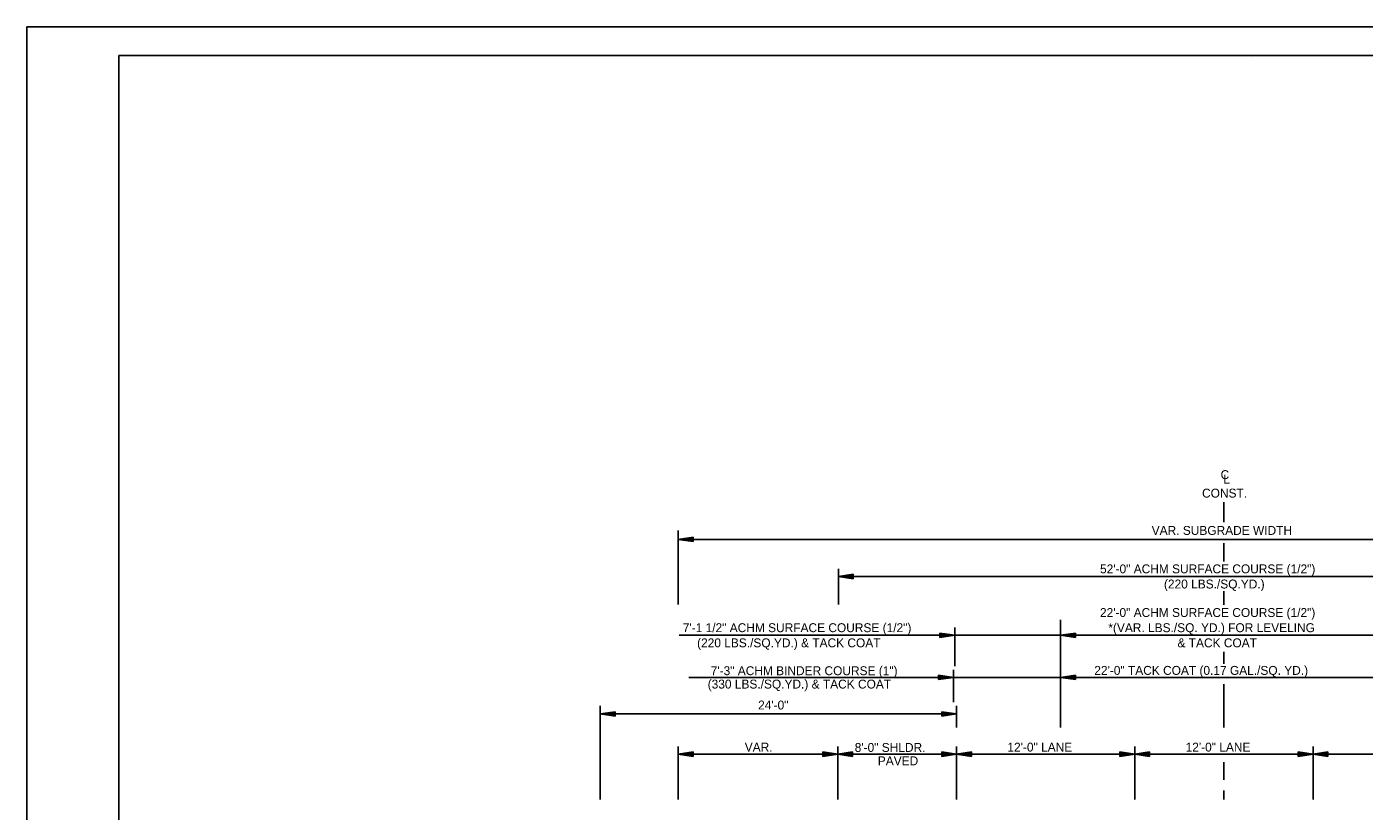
# Model space of a CAD drawing. Extents: x 1371763 to 1372860, y 385599 to 385872.
# Drawn here: x 1371763.4 to 1371853.4, y 385652.4 to 385705.3 of the extents above; entities that cross this region are included whole.
import ezdxf

# ---------------------------------------------------------------- set-up
doc = ezdxf.new("R2010")
doc.units = 0
for name, color, linetype in [('R_Border', 7, 'Continuous'), ('R_Draft', 7, 'Continuous'), ('R_No Plot', 7, 'Continuous')]:
    doc.layers.add(name, color=color, linetype=linetype)

msp = doc.modelspace()

# ---------------------------------------------------------------- linework, layer by layer
at = {"layer": 'R_Border'}
for p, q in [((1371769.555, 385703.307), (1371927.645, 385703.307)), ((1371769.555, 385600.577), (1371769.555, 385703.307)), ((1371845.815, 385703.177), (1371845.815, 385703.177)), ((1371845.815, 385703.177), (1371845.815, 385703.177))]:
    msp.add_line(p, q, dxfattribs=at)
at = {"layer": 'R_Draft'}
for p, q in [((1371843.971, 385671.877), (1371843.971, 385673.227)), ((1371807.224, 385666.329), (1371807.224, 385671.327)), ((1371808.224, 385670.877), (1371807.224, 385670.727)), ((1371807.224, 385670.727), (1371878.536, 385670.727)), ((1371808.224, 385670.577), (1371807.224, 385670.727)), ((1371808.224, 385670.852), (1371807.391, 385670.727)), ((1371808.224, 385670.602), (1371807.391, 385670.727)), ((1371808.224, 385670.827), (1371807.563, 385670.727)), ((1371808.224, 385670.628), (1371807.563, 385670.727)), ((1371808.224, 385670.802), (1371807.73, 385670.727)), ((1371808.224, 385670.653), (1371807.73, 385670.727)), ((1371808.224, 385670.776), (1371807.899, 385670.727)), ((1371808.224, 385670.678), (1371807.899, 385670.727)), ((1371808.224, 385670.751), (1371808.066, 385670.727)), ((1371808.224, 385670.704), (1371808.066, 385670.727)), ((1371808.224, 385670.877), (1371808.224, 385670.577)), ((1371843.971, 385669.227), (1371843.971, 385670.477)), ((1371818.01, 385666.329), (1371818.01, 385668.737)), ((1371819.01, 385668.377), (1371818.01, 385668.227)), ((1371818.01, 385668.227), (1371869.931, 385668.227)), ((1371819.01, 385668.077), (1371818.01, 385668.227)), ((1371819.01, 385668.352), (1371818.177, 385668.227)), ((1371819.01, 385668.102), (1371818.177, 385668.227)), ((1371819.01, 385668.327), (1371818.349, 385668.227)), ((1371819.01, 385668.128), (1371818.349, 385668.227)), ((1371819.01, 385668.302), (1371818.516, 385668.227)), ((1371819.01, 385668.153), (1371818.516, 385668.227)), ((1371819.01, 385668.276), (1371818.685, 385668.227)), ((1371819.01, 385668.178), (1371818.685, 385668.227)), ((1371819.01, 385668.251), (1371818.852, 385668.227)), ((1371819.01, 385668.204), (1371818.852, 385668.227)), ((1371819.01, 385668.377), (1371819.01, 385668.077)), ((1371843.971, 385666.319), (1371843.971, 385667.227)), ((1371832.971, 385658.059), (1371832.971, 385665.297)), ((1371807.295, 385664.265), (1371832.971, 385664.265)), ((1371824.847, 385664.415), (1371825.847, 385664.265)), ((1371824.847, 385664.115), (1371824.847, 385664.415)), ((1371824.847, 385664.39), (1371825.68, 385664.265)), ((1371824.847, 385664.365), (1371825.508, 385664.265)), ((1371824.847, 385664.34), (1371825.342, 385664.265)), ((1371824.847, 385664.314), (1371825.172, 385664.265)), ((1371824.847, 385664.289), (1371825.005, 385664.265)), ((1371824.847, 385664.115), (1371825.847, 385664.265)), ((1371824.847, 385664.217), (1371825.172, 385664.265)), ((1371824.847, 385664.166), (1371825.508, 385664.265)), ((1371824.847, 385664.14), (1371825.68, 385664.265)), ((1371824.847, 385664.191), (1371825.342, 385664.265)), ((1371824.847, 385664.242), (1371825.005, 385664.265)), ((1371825.849, 385664.785), (1371825.849, 385662.177)), ((1371833.971, 385664.415), (1371832.971, 385664.265)), ((1371832.971, 385664.265), (1371854.971, 385664.266)), ((1371833.971, 385664.115), (1371832.971, 385664.265)), ((1371833.971, 385664.39), (1371833.138, 385664.265)), ((1371833.971, 385664.14), (1371833.138, 385664.265)), ((1371833.971, 385664.365), (1371833.31, 385664.265)), ((1371833.971, 385664.166), (1371833.31, 385664.265)), ((1371833.971, 385664.34), (1371833.476, 385664.265)), ((1371833.971, 385664.191), (1371833.476, 385664.265)), ((1371833.971, 385664.314), (1371833.646, 385664.265)), ((1371833.971, 385664.217), (1371833.646, 385664.265)), ((1371833.971, 385664.289), (1371833.813, 385664.265)), ((1371833.971, 385664.242), (1371833.813, 385664.265)), ((1371833.971, 385664.115), (1371833.971, 385664.415)), ((1371843.967, 385662.347), (1371843.967, 385663.157)), ((1371807.929, 385661.427), (1371832.971, 385661.427)), ((1371824.749, 385661.577), (1371825.749, 385661.427)), ((1371824.749, 385661.277), (1371824.749, 385661.577)), ((1371824.749, 385661.552), (1371825.582, 385661.427)), ((1371824.749, 385661.527), (1371825.41, 385661.427)), ((1371824.749, 385661.502), (1371825.244, 385661.427)), ((1371824.749, 385661.476), (1371825.074, 385661.427)), ((1371824.749, 385661.451), (1371824.907, 385661.427)), ((1371824.749, 385661.277), (1371825.749, 385661.427)), ((1371824.749, 385661.379), (1371825.074, 385661.427)), ((1371824.749, 385661.328), (1371825.41, 385661.427)), ((1371824.749, 385661.302), (1371825.582, 385661.427)), ((1371824.749, 385661.353), (1371825.244, 385661.427)), ((1371824.749, 385661.404), (1371824.907, 385661.427)), ((1371825.749, 385661.947), (1371825.749, 385659.762)), ((1371833.971, 385661.577), (1371832.971, 385661.427)), ((1371833.971, 385661.277), (1371832.971, 385661.427)), ((1371832.971, 385661.427), (1371854.971, 385661.427)), ((1371833.971, 385661.552), (1371833.138, 385661.427)), ((1371833.971, 385661.302), (1371833.138, 385661.427)), ((1371833.971, 385661.527), (1371833.31, 385661.427)), ((1371833.971, 385661.328), (1371833.31, 385661.427)), ((1371833.971, 385661.502), (1371833.476, 385661.427)), ((1371833.971, 385661.353), (1371833.476, 385661.427)), ((1371833.971, 385661.476), (1371833.646, 385661.427)), ((1371833.971, 385661.379), (1371833.646, 385661.427)), ((1371833.971, 385661.451), (1371833.813, 385661.427)), ((1371833.971, 385661.404), (1371833.813, 385661.427)), ((1371833.971, 385661.277), (1371833.971, 385661.577)), ((1371843.968, 385658.059), (1371843.967, 385660.967)), ((1371801.968, 385653.207), (1371801.968, 385659.505)), ((1371825.968, 385658.059), (1371825.968, 385659.505)), ((1371802.968, 385659.115), (1371801.968, 385658.965)), ((1371802.968, 385658.815), (1371801.968, 385658.965)), ((1371825.968, 385658.965), (1371801.968, 385658.965)), ((1371802.968, 385659.09), (1371802.135, 385658.965)), ((1371802.968, 385658.84), (1371802.135, 385658.965)), ((1371802.968, 385659.064), (1371802.307, 385658.965)), ((1371802.968, 385658.865), (1371802.307, 385658.965)), ((1371802.968, 385659.039), (1371802.473, 385658.965)), ((1371802.968, 385658.89), (1371802.473, 385658.965)), ((1371802.968, 385659.013), (1371802.643, 385658.965)), ((1371802.968, 385658.916), (1371802.643, 385658.965)), ((1371802.968, 385658.988), (1371802.81, 385658.965)), ((1371802.968, 385658.941), (1371802.81, 385658.965)), ((1371802.968, 385659.115), (1371802.968, 385658.815)), ((1371824.968, 385659.115), (1371825.968, 385658.965)), ((1371824.968, 385659.115), (1371824.968, 385658.815)), ((1371824.968, 385659.09), (1371825.801, 385658.965)), ((1371824.968, 385659.064), (1371825.629, 385658.965)), ((1371824.968, 385659.039), (1371825.462, 385658.965)), ((1371824.968, 385659.013), (1371825.293, 385658.965)), ((1371824.968, 385658.988), (1371825.126, 385658.965)), ((1371824.968, 385658.815), (1371825.968, 385658.965)), ((1371824.968, 385658.916), (1371825.293, 385658.965)), ((1371824.968, 385658.865), (1371825.629, 385658.965)), ((1371824.968, 385658.84), (1371825.801, 385658.965)), ((1371824.968, 385658.89), (1371825.462, 385658.965)), ((1371824.968, 385658.941), (1371825.126, 385658.965)), ((1371807.224, 385653.207), (1371807.224, 385656.765)), ((1371808.224, 385656.408), (1371807.224, 385656.258)), ((1371807.224, 385656.258), (1371817.968, 385656.258)), ((1371808.224, 385656.108), (1371807.224, 385656.258)), ((1371808.224, 385656.383), (1371807.391, 385656.258)), ((1371808.224, 385656.133), (1371807.391, 385656.258)), ((1371808.224, 385656.358), (1371807.563, 385656.258)), ((1371808.224, 385656.159), (1371807.563, 385656.258)), ((1371808.224, 385656.333), (1371807.73, 385656.258)), ((1371808.224, 385656.184), (1371807.73, 385656.258)), ((1371808.224, 385656.307), (1371807.899, 385656.258)), ((1371808.224, 385656.21), (1371807.899, 385656.258)), ((1371808.224, 385656.282), (1371808.066, 385656.258)), ((1371808.224, 385656.235), (1371808.066, 385656.258)), ((1371808.224, 385656.108), (1371808.224, 385656.408)), ((1371816.968, 385656.408), (1371817.968, 385656.258)), ((1371816.968, 385656.108), (1371816.968, 385656.408)), ((1371816.968, 385656.383), (1371817.801, 385656.258)), ((1371816.968, 385656.358), (1371817.629, 385656.258)), ((1371816.968, 385656.333), (1371817.462, 385656.258)), ((1371816.968, 385656.307), (1371817.293, 385656.258)), ((1371816.968, 385656.282), (1371817.126, 385656.258)), ((1371816.968, 385656.108), (1371817.968, 385656.258)), ((1371816.968, 385656.21), (1371817.293, 385656.258)), ((1371816.968, 385656.159), (1371817.629, 385656.258)), ((1371816.968, 385656.133), (1371817.801, 385656.258)), ((1371816.968, 385656.184), (1371817.462, 385656.258)), ((1371816.968, 385656.235), (1371817.126, 385656.258)), ((1371817.968, 385653.207), (1371817.968, 385656.765)), ((1371818.968, 385656.408), (1371817.968, 385656.258)), ((1371817.968, 385656.258), (1371825.968, 385656.258)), ((1371818.968, 385656.108), (1371817.968, 385656.258)), ((1371818.968, 385656.383), (1371818.135, 385656.258)), ((1371818.968, 385656.133), (1371818.135, 385656.258)), ((1371818.968, 385656.358), (1371818.307, 385656.258)), ((1371818.968, 385656.159), (1371818.307, 385656.258)), ((1371818.968, 385656.333), (1371818.473, 385656.258)), ((1371818.968, 385656.184), (1371818.473, 385656.258)), ((1371818.968, 385656.307), (1371818.643, 385656.258)), ((1371818.968, 385656.21), (1371818.643, 385656.258)), ((1371818.968, 385656.282), (1371818.81, 385656.258)), ((1371818.968, 385656.235), (1371818.81, 385656.258)), ((1371818.968, 385656.108), (1371818.968, 385656.408)), ((1371824.968, 385656.408), (1371825.968, 385656.258)), ((1371824.968, 385656.108), (1371824.968, 385656.408)), ((1371824.968, 385656.383), (1371825.801, 385656.258)), ((1371824.968, 385656.358), (1371825.629, 385656.258)), ((1371824.968, 385656.333), (1371825.462, 385656.258)), ((1371824.968, 385656.307), (1371825.293, 385656.258)), ((1371824.968, 385656.282), (1371825.126, 385656.258)), ((1371824.968, 385656.108), (1371825.968, 385656.258)), ((1371824.968, 385656.21), (1371825.293, 385656.258)), ((1371824.968, 385656.159), (1371825.629, 385656.258)), ((1371824.968, 385656.133), (1371825.801, 385656.258)), ((1371824.968, 385656.184), (1371825.462, 385656.258)), ((1371824.968, 385656.235), (1371825.126, 385656.258)), ((1371825.968, 385653.207), (1371825.968, 385656.765)), ((1371826.968, 385656.408), (1371825.968, 385656.258)), ((1371825.968, 385656.258), (1371837.968, 385656.258)), ((1371826.968, 385656.108), (1371825.968, 385656.258)), ((1371826.968, 385656.383), (1371826.135, 385656.258)), ((1371826.968, 385656.133), (1371826.135, 385656.258)), ((1371826.968, 385656.358), (1371826.307, 385656.258)), ((1371826.968, 385656.159), (1371826.307, 385656.258)), ((1371826.968, 385656.333), (1371826.473, 385656.258)), ((1371826.968, 385656.184), (1371826.473, 385656.258)), ((1371826.968, 385656.307), (1371826.643, 385656.258)), ((1371826.968, 385656.21), (1371826.643, 385656.258)), ((1371826.968, 385656.282), (1371826.81, 385656.258)), ((1371826.968, 385656.235), (1371826.81, 385656.258)), ((1371826.968, 385656.108), (1371826.968, 385656.408)), ((1371836.968, 385656.408), (1371837.968, 385656.258)), ((1371836.968, 385656.108), (1371836.968, 385656.408)), ((1371836.968, 385656.383), (1371837.801, 385656.258)), ((1371836.968, 385656.358), (1371837.629, 385656.258)), ((1371836.968, 385656.333), (1371837.462, 385656.258)), ((1371836.968, 385656.307), (1371837.293, 385656.258)), ((1371836.968, 385656.282), (1371837.126, 385656.258)), ((1371836.968, 385656.108), (1371837.968, 385656.258)), ((1371836.968, 385656.21), (1371837.293, 385656.258)), ((1371836.968, 385656.159), (1371837.629, 385656.258)), ((1371836.968, 385656.133), (1371837.801, 385656.258)), ((1371836.968, 385656.184), (1371837.462, 385656.258)), ((1371836.968, 385656.235), (1371837.126, 385656.258)), ((1371837.968, 385653.207), (1371837.968, 385656.765)), ((1371838.968, 385656.408), (1371837.968, 385656.258)), ((1371838.968, 385656.108), (1371837.968, 385656.258)), ((1371837.968, 385656.258), (1371849.968, 385656.258)), ((1371838.968, 385656.383), (1371838.135, 385656.258)), ((1371838.968, 385656.133), (1371838.135, 385656.258)), ((1371838.968, 385656.358), (1371838.307, 385656.258)), ((1371838.968, 385656.159), (1371838.307, 385656.258)), ((1371838.968, 385656.333), (1371838.473, 385656.258)), ((1371838.968, 385656.184), (1371838.473, 385656.258)), ((1371838.968, 385656.307), (1371838.643, 385656.258)), ((1371838.968, 385656.21), (1371838.643, 385656.258)), ((1371838.968, 385656.282), (1371838.81, 385656.258)), ((1371838.968, 385656.235), (1371838.81, 385656.258)), ((1371838.968, 385656.108), (1371838.968, 385656.408)), ((1371848.968, 385656.408), (1371849.968, 385656.258)), ((1371848.968, 385656.108), (1371848.968, 385656.408)), ((1371848.968, 385656.383), (1371849.801, 385656.258)), ((1371848.968, 385656.358), (1371849.629, 385656.258)), ((1371848.968, 385656.333), (1371849.462, 385656.258)), ((1371848.968, 385656.307), (1371849.293, 385656.258)), ((1371848.968, 385656.282), (1371849.126, 385656.258)), ((1371848.968, 385656.108), (1371849.968, 385656.258)), ((1371848.968, 385656.21), (1371849.293, 385656.258)), ((1371848.968, 385656.159), (1371849.629, 385656.258)), ((1371848.968, 385656.133), (1371849.801, 385656.258)), ((1371848.968, 385656.184), (1371849.462, 385656.258)), ((1371848.968, 385656.235), (1371849.126, 385656.258)), ((1371849.968, 385653.207), (1371849.968, 385656.765)), ((1371850.968, 385656.408), (1371849.968, 385656.258)), ((1371849.968, 385656.258), (1371861.968, 385656.258)), ((1371850.968, 385656.108), (1371849.968, 385656.258)), ((1371850.968, 385656.383), (1371850.135, 385656.258)), ((1371850.968, 385656.133), (1371850.135, 385656.258)), ((1371850.968, 385656.358), (1371850.307, 385656.258)), ((1371850.968, 385656.159), (1371850.307, 385656.258)), ((1371850.968, 385656.333), (1371850.473, 385656.258)), ((1371850.968, 385656.184), (1371850.473, 385656.258)), ((1371850.968, 385656.307), (1371850.643, 385656.258)), ((1371850.968, 385656.21), (1371850.643, 385656.258)), ((1371850.968, 385656.282), (1371850.81, 385656.258)), ((1371850.968, 385656.235), (1371850.81, 385656.258)), ((1371850.968, 385656.108), (1371850.968, 385656.408)), ((1371843.968, 385654.523), (1371843.967, 385655.728)), ((1371843.971, 385653.207), (1371843.971, 385653.815))]:
    msp.add_line(p, q, dxfattribs=at)
at = {"layer": 'R_No Plot'}
msp.add_line((1371763.354, 385705.254), (1371930.021, 385705.254), dxfattribs=at)
for points in [[(1371763.351, 385705.254), (1371930.021, 385705.254), (1371930.021, 385598.585), (1371763.351, 385598.585)], [(1371886.515, 385703.307), (1371896.325, 385703.307), (1371896.325, 385698.367), (1371904.381, 385698.367), (1371915.98, 385698.367), (1371916.041, 385684.288), (1371927.645, 385684.288), (1371927.645, 385600.577), (1371769.555, 385600.577), (1371769.555, 385703.307)]]:
    msp.add_lwpolyline(points, close=True, dxfattribs=at)

# ---------------------------------------------------------------- texts
at = {"layer": 'R_Draft'}
for s, p in [('C', (1371843.746, 385674.784)), ('L', (1371843.932, 385674.484)), ('CONST.', (1371842.497, 385673.54)), ('VAR. SUBGRADE WIDTH', (1371839.105, 385671.027)), ('52\'-0" ACHM SURFACE COURSE (1/2")', (1371835.627, 385668.437)), ('(220 LBS./SQ.YD.)', (1371839.931, 385667.417)), ('22\'-0" ACHM SURFACE COURSE (1/2")', (1371835.624, 385665.495)), ('7\'-1 1/2" ACHM SURFACE COURSE (1/2")', (1371807.531, 385664.475)), ('*(VAR. LBS./SQ. YD.) FOR LEVELING', (1371836.184, 385664.475)), ('(220 LBS./SQ.YD.) & TACK COAT', (1371808.493, 385663.455)), ('& TACK COAT', (1371840.842, 385663.455)), ('7\'-3" ACHM BINDER COURSE (1")', (1371809.411, 385661.577)), ('22\'-0" TACK COAT (0.17 GAL./SQ. YD.)', (1371835.241, 385661.599)), ('(330 LBS./SQ.YD.) & TACK COAT', (1371809.205, 385660.677)), ('24\'-0"', (1371812.6, 385659.265)), ('VAR.', (1371811.701, 385656.43)), ('8\'-0" SHLDR.', (1371819.107, 385656.408)), ('12\'-0" LANE', (1371829.39, 385656.43)), ('12\'-0" LANE', (1371841.39, 385656.43)), ('PAVED', (1371820.664, 385655.508))]:
    msp.add_text(s, height=0.6, rotation=360, dxfattribs=at).set_placement(p)

doc.saveas('drawing.dxf')
